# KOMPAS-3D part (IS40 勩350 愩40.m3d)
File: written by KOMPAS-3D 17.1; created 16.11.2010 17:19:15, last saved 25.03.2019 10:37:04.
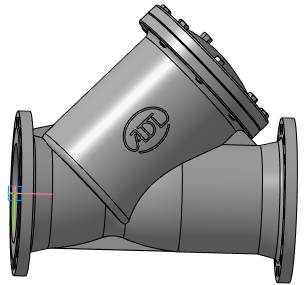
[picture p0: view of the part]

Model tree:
1. Плоскость XY
2. Плоскость ZX
3. Плоскость ZY
4. Ось X
5. Ось Y
6. Ось Z
7. Начало координат
8. Операция без истории:3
